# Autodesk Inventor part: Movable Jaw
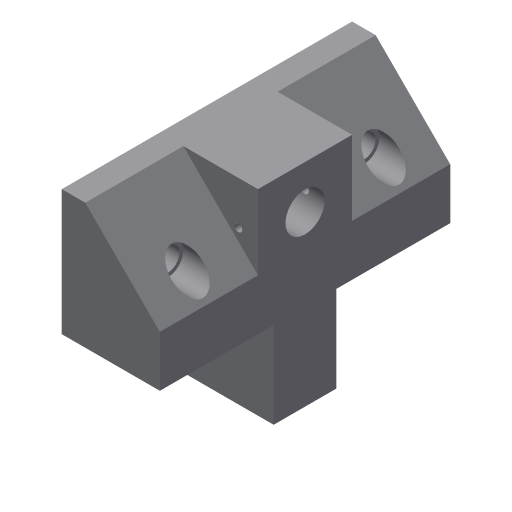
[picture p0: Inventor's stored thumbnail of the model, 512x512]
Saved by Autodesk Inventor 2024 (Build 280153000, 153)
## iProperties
Shininess: 77.0
Length Units: 11269
Angle Units: 11279
Time Units: 11290
Mass Units: 11283
Length Display Precision: 3
Angle Display Precision: 2
Created: 2002-02
Part Number: Movable Jaw
Document SubType Name: Modeling
Designer: ***
Density: 1 g/cm^3
Material: Generic
Appearance: Default
Density: 0.0
Volumn: 0.0
Area: 0.0
PropertySet Name: Model Information
Control State: 0
Master: False
Checked Out: False
Author: ***
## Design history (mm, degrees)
sketch "Sketch2"
  geometry: L1 (2.39, 41.509)-(2.39, 9.509); L2 (2.39, 9.509)-(-22.61, 9.509); L3 (-22.61, 9.509)-(-22.61, 22.509); L4 (-22.61, 22.509)-(-3.61, 41.509); L5 (-3.61, 41.509)-(2.39, 41.509)
  constraints: 10 end point, 2 parallel, 1 perpendicular, 1 vertical
  dimensions: "d0" = 25 distance of L1.end L2.end; "d2" = 13 distance of L2.end L3.end; "d3" = 32 distance between parallel lines of L5 L2; "d4" = 6 distance of L4.end L1.start
extrude "Extrusion1" new body sketch "Sketch2" stored distance "d5" = 74; taper "d6" = 0 deg
sketch "Sketch3"
  geometry: L1 (-19, 25)-(11, 25); L2 (11, 25)-(11, 49); L3 (11, 49)-(-19, 49); L4 (-19, 49)-(-19, 25); L5 (0, 0)-(13, 0) reference; L6 (-19, 74)-(-19, 0) reference; L7 (11.924, 29)-(35, 29); L8 (35, 29)-(35, 45); L9 (35, 45)-(11.924, 45); L10 (11.924, 45)-(11.924, 29); L11 (13, 74)-(13, 0) reference
  constraints: 16 end point, 4 parallel, 2 horizontal, 2 perpendicular, 1 collinear
  dimensions: "d7" = 24 distance of L3.end L1.start; "d8" = 30 distance of L1.start L1.end; "d9" = 25 distance between parallel lines of L5 L1; "d10" = 16 distance of L7.end L8.end; "d11" = 4 distance between parallel lines of L3 L9; "d12" = 22 distance between parallel lines of L11 L8
extrude "Extrusion2" join sketch "Sketch3" distance "d13" = 25; taper "d14" = 0 deg
sketch "Sketch4"
  geometry: L1 (-19, -25)-(-19, -49) reference; L2 (-19, -49)-(0, -49) reference; 1 further point
  dimensions: "d15" = 11 distance from line of L1 point (-8, -37); "d16" = 12 distance from line of L2 point (-8, -37)
hole "Hole1" sketch "Sketch4" diameter "d17" = 10; stored, may be unused: countersink angle "d21" = 82 deg, drill point angle "d23" = 0 deg; dims "d18" = 6, "d19" = 4, "d20" = 2, "d22" = 13
sketch "Sketch5"
  geometry: L1 (-19, -49)-(-19, -74) reference; L2 (0, -74)-(13, -74) reference; 1 further point
  dimensions: "d24" = 14 distance from line of L1 point (-5, -62); "d25" = 12 distance from line of L2 point (-5, -62)
hole "Hole2" sketch "Sketch5" diameter "d26" = 6; stored, may be unused: countersink angle "d30" = 82 deg, drill point angle "d32" = 0 deg; dims "d27" = 6, "d28" = 8, "d29" = 10, "d31" = 13
mirror "Mirror1"
sketch "Sketch6"
  geometry: L1 (0, 19)-(0, 0) reference; 1 further point
  dimensions: "d33" = 5 distance from line of L1 point (-5, 8); "d34" = 11 vertical distance of L1.start point (-5, 8)
hole "Hole3" sketch "Sketch6" diameter "d35" = 2; stored, may be unused: countersink angle "d39" = 82 deg, drill point angle "d41" = 0 deg; dims "d36" = 6, "d37" = 8, "d38" = 10, "d40" = 13
body "Solid1"
